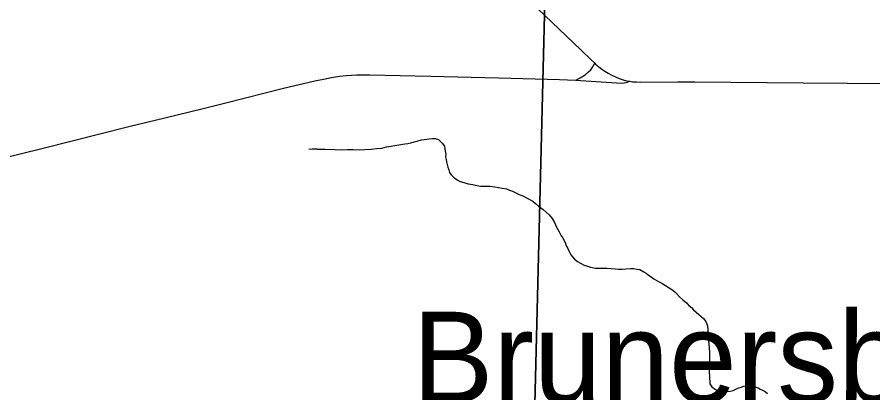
# Model space of a CAD drawing. Extents: x 0 to 34, y 0 to 22.
# Drawn here: x 4.023 to 4.767, y 19.941 to 20.268 of the extents above; entities that cross this region are included whole.
import ezdxf

# ---------------------------------------------------------------- set-up
doc = ezdxf.new("R2010")
doc.units = 0
for name, color, linetype in [('GM_X_Interchange_Ramps', 7, 'Continuous'), ('GM_X_Minor_River', 7, 'Continuous'), ('GM_X_Section', 7, 'Continuous'), ('GM_X_State_Route', 7, 'Continuous'), ('GM_X_Unincorporated_Text', 7, 'Continuous')]:
    doc.layers.add(name, color=color, linetype=linetype)

msp = doc.modelspace()

# ---------------------------------------------------------------- linework, layer by layer
at = {"layer": 'GM_X_Interchange_Ramps'}
msp.add_lwpolyline([(4.50878, 20.2129), (4.54859, 20.21023), (4.55085, 20.21036), (4.55263, 20.21065), (4.55565, 20.21181)], dxfattribs=at)
at = {"layer": 'GM_X_Minor_River'}
for points in [[(4.27702, 20.15309), (4.28423, 20.15291), (4.28006, 20.15302), (4.28423, 20.15291), (4.29069, 20.15275), (4.29942, 20.15253), (4.30549, 20.15237), (4.31043, 20.15263), (4.31537, 20.1525), (4.32068, 20.15237), (4.32563, 20.15262), (4.33096, 20.15286), (4.33591, 20.1535), (4.34047, 20.15376), (4.3443, 20.15481), (4.34849, 20.15546), (4.35155, 20.15614), (4.36032, 20.15744), (4.36299, 20.15775), (4.36566, 20.15844), (4.36834, 20.15913), (4.37178, 20.16018), (4.37484, 20.16086), (4.37713, 20.16119), (4.37942, 20.16151), (4.38132, 20.16184), (4.38437, 20.16214), (4.38665, 20.16208), (4.38966, 20.16125), (4.39263, 20.15813), (4.39484, 20.15542), (4.39516, 20.15314), (4.39549, 20.15123), (4.3958, 20.14856), (4.39575, 20.14629), (4.39607, 20.144), (4.39639, 20.14171), (4.39709, 20.13942), (4.39779, 20.13712), (4.3985, 20.13483), (4.39919, 20.13253), (4.40067, 20.1306), (4.40251, 20.12865), (4.40587, 20.12629), (4.40849, 20.1247), (4.41151, 20.12387), (4.41528, 20.12263), (4.41944, 20.12215), (4.42284, 20.1213), (4.42625, 20.12084), (4.43004, 20.12074), (4.43422, 20.12063), (4.43839, 20.12015), (4.44179, 20.11968), (4.44481, 20.11885), (4.4486, 20.11837), (4.45123, 20.11717), (4.45386, 20.11634), (4.45611, 20.11514), (4.45949, 20.11354), (4.46288, 20.11232), (4.4715, 20.10754), (4.47373, 20.10559), (4.47633, 20.10324), (4.48043, 20.10048), (4.48303, 20.09814), (4.48564, 20.09579), (4.48821, 20.09269), (4.49041, 20.08922), (4.4922, 20.085), (4.49438, 20.08115), (4.49619, 20.07768), (4.49766, 20.07575), (4.49837, 20.07383), (4.49946, 20.0719), (4.50053, 20.06884), (4.50199, 20.06653), (4.50306, 20.06384), (4.50451, 20.06115), (4.50598, 20.05921), (4.50783, 20.05727), (4.51044, 20.0553), (4.51306, 20.05372), (4.51606, 20.05212), (4.51907, 20.05129), (4.52171, 20.05046), (4.52587, 20.04959), (4.52891, 20.04952), (4.53271, 20.04942), (4.53574, 20.04934), (4.53954, 20.04925), (4.54294, 20.04878), (4.54598, 20.04871), (4.54902, 20.04863), (4.55244, 20.04892), (4.55625, 20.0492), (4.55929, 20.04913), (4.56193, 20.04868), (4.56458, 20.04823), (4.56795, 20.04625), (4.56982, 20.04506)], [(4.56982, 20.04506), (4.57206, 20.04349), (4.5743, 20.04191), (4.57654, 20.04034), (4.57879, 20.03914), (4.58066, 20.03796), (4.58254, 20.03715), (4.58441, 20.03596), (4.58664, 20.03439), (4.593, 20.03043), (4.59486, 20.02887), (4.59672, 20.0273), (4.59893, 20.02459), (4.6019, 20.02185), (4.60488, 20.0195), (4.6071, 20.01716), (4.60933, 20.01521), (4.61118, 20.01327), (4.61341, 20.01131), (4.61564, 20.00936), (4.61787, 20.0074), (4.61973, 20.00584), (4.62194, 20.00312), (4.62336, 19.99929), (4.62367, 19.99624), (4.62395, 19.99244), (4.62385, 19.98827), (4.62448, 19.98331), (4.62477, 19.97989), (4.62508, 19.97684), (4.62499, 19.97343), (4.62489, 19.96964), (4.62479, 19.96546), (4.62469, 19.96167), (4.62461, 19.95863), (4.62493, 19.95597), (4.62486, 19.95331), (4.62519, 19.95141), (4.62513, 19.94913), (4.62696, 19.94642), (4.63032, 19.94406), (4.6322, 19.94325), (4.63485, 19.94281), (4.6375, 19.94236), (4.64016, 19.94229), (4.64282, 19.9426), (4.6455, 19.9433), (4.64742, 19.94401), (4.64972, 19.94509), (4.65241, 19.94616), (4.65471, 19.94686), (4.65737, 19.94717), (4.66118, 19.94745), (4.66307, 19.94703), (4.66533, 19.94621), (4.66721, 19.9454), (4.66907, 19.94422), (4.67095, 19.94341), (4.6732, 19.94222), (4.67544, 19.94064)]]:
    msp.add_lwpolyline(points, dxfattribs=at)
at = {"layer": 'GM_X_Section'}
for points in [[(3.47915, 20.47067), (4.48621, 20.45658), (4.46097, 19.44139), (3.45491, 19.46644)], [(4.48621, 20.45658), (5.48293, 20.43816), (5.4561, 19.43741), (4.46097, 19.44139)]]:
    msp.add_lwpolyline(points, close=True, dxfattribs=at)
at = {"layer": 'GM_X_State_Route'}
for points in [[(4.34094, 20.39756), (4.34467, 20.39419), (4.38408, 20.35897), (4.40678, 20.33775), (4.42987, 20.31694), (4.46849, 20.28176), (4.47624, 20.27439), (4.48788, 20.26333), (4.51343, 20.2388), (4.52204, 20.23059), (4.52523, 20.22759)], [(3.95873, 20.13227), (4.04509, 20.15336), (4.12164, 20.17271), (4.15184, 20.18005), (4.18502, 20.18828), (4.20491, 20.19325), (4.25499, 20.20572), (4.28226, 20.2121), (4.29099, 20.21393), (4.29811, 20.21532), (4.30374, 20.21618), (4.3093, 20.21677), (4.31383, 20.21714), (4.31867, 20.21742), (4.3299, 20.21732), (4.38273, 20.21625), (4.44177, 20.21471), (4.4946, 20.21339), (4.50154, 20.21306), (4.50878, 20.2129), (4.51255, 20.21489), (4.51693, 20.21754), (4.51993, 20.21997), (4.52179, 20.22188), (4.52303, 20.22341), (4.52431, 20.22555), (4.52523, 20.22759)], [(4.52523, 20.22759), (4.52604, 20.22683), (4.52889, 20.22447), (4.53149, 20.22244), (4.53418, 20.22066), (4.53694, 20.21895), (4.54027, 20.21717), (4.54345, 20.21564), (4.5466, 20.21436), (4.54903, 20.21344), (4.55095, 20.21287), (4.5531, 20.21229), (4.55565, 20.21181)], [(4.55565, 20.21181), (4.55821, 20.21149), (4.56147, 20.21124), (4.5648, 20.21116), (4.59748, 20.21127)], [(4.59748, 20.21127), (4.61234, 20.21131), (4.70625, 20.21044), (4.78337, 20.20996), (4.79746, 20.20981)]]:
    msp.add_lwpolyline(points, dxfattribs=at)

# ---------------------------------------------------------------- texts
at = {"layer": 'GM_X_Unincorporated_Text'}
msp.add_text('Brunersburg', height=0.0789773, rotation=0.00001, dxfattribs=at).set_placement((4.36681, 19.93271))

doc.saveas('drawing.dxf')
